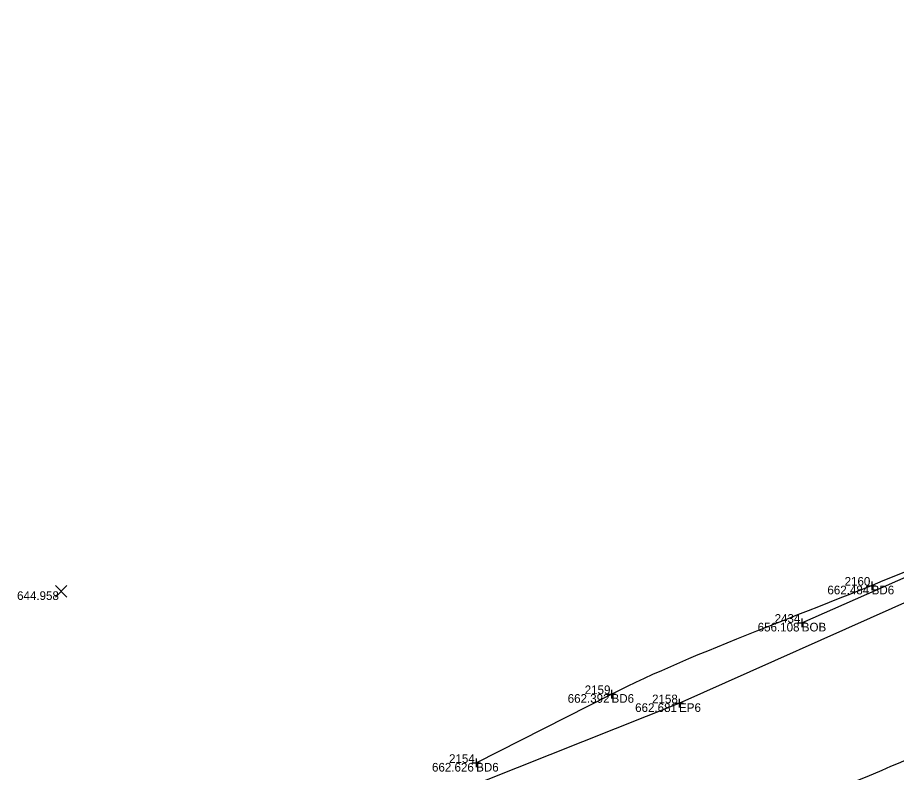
# Model space of a CAD drawing. Extents: x 2197382 to 2204062, y 634117 to 636522.
# Drawn here: x 2202361.4 to 2202463, y 635224.5 to 635311.8 of the extents above; entities that cross this region are included whole.
import ezdxf

# ---------------------------------------------------------------- set-up
doc = ezdxf.new("R2010")
doc.units = 0
for name, color, linetype in [('_CIVIL_CONSTRUCTION', 7, 'Continuous'), ('BR_X_SV_Bottom_of_Beam', 7, 'Continuous'), ('BR_X_SV_Bottom_of_Beam_Text', 7, 'Continuous'), ('BR_X_SV_Deck_Top', 7, 'Continuous'), ('BR_X_SV_Deck_Top_Text', 7, 'Continuous'), ('GE_P_Alignment_100_Distances', 7, 'Continuous'), ('GE_X_Alignment', 7, 'Continuous'), ('RW_X_CL_100_Curve_Data', 7, 'Continuous'), ('SH_Border', 7, 'Continuous'), ('SH_Cut_Line', 7, 'Continuous'), ('SH_Data', 7, 'Continuous')]:
    doc.layers.add(name, color=color, linetype=linetype)

msp = doc.modelspace()

# ---------------------------------------------------------------- linework, layer by layer
at = {"layer": '_CIVIL_CONSTRUCTION'}
for p, q in [((2202460.13, 635246.62), (2202460.13, 635245.62)), ((2202459.63, 635246.12), (2202460.63, 635246.12)), ((2202460.13, 635246.12), (2202460.13, 635246.12)), ((2202452.05, 635242.33), (2202452.05, 635241.33)), ((2202451.55, 635241.83), (2202452.55, 635241.83)), ((2202452.05, 635241.83), (2202452.05, 635241.83)), ((2202429.55, 635233.59), (2202430.55, 635233.59)), ((2202430.05, 635234.09), (2202430.05, 635233.09)), ((2202430.05, 635233.59), (2202430.05, 635233.59)), ((2202437.36, 635232.53), (2202438.36, 635232.53)), ((2202437.86, 635233.03), (2202437.86, 635232.03)), ((2202437.86, 635232.53), (2202437.86, 635232.53)), ((2202414.4, 635226.14), (2202414.4, 635225.14)), ((2202413.9, 635225.64), (2202414.9, 635225.64)), ((2202414.4, 635225.64), (2202414.4, 635225.64))]:
    msp.add_line(p, q, dxfattribs=at)
at = {"layer": 'BR_X_SV_Bottom_of_Beam'}
msp.add_lwpolyline([(2202452.05, 635241.83), (2202486.67, 635257.09), (2202513.32, 635270.74)], dxfattribs=at)
at = {"layer": 'BR_X_SV_Deck_Top'}
msp.add_line((2202414.4, 635225.64), (2202430.05, 635233.59), dxfattribs=at)
for points in [[(2202430.05, 635233.59), (2202439.74, 635238.51), (2202466.34, 635247.69), (2202507.17, 635268.03), (2202543.72, 635286.4), (2202574.88, 635303.71), (2202604.91, 635320.16), (2202634.13, 635339.4), (2202663.02, 635358.59), (2202692.44, 635376.51), (2202729.25, 635404.45), (2202755.81, 635426.42), (2202769.74, 635438.84)], [(2202458.05, 635216.68), (2202477.12, 635219.98), (2202511.72, 635243.78), (2202554.96, 635262.3), (2202588.01, 635280.67), (2202608.34, 635292.39), (2202640.83, 635312.14), (2202668.15, 635329.95), (2202698.57, 635351.31), (2202722.13, 635368.65), (2202754.6, 635393.43), (2202777.49, 635412.29), (2202789.61, 635422.64)]]:
    msp.add_open_spline(points, degree=3, dxfattribs=at)
at = {"layer": 'GE_P_Alignment_100_Distances'}
for p, q in [((2202437.86, 635232.53), (2202483.16, 635252.76)), ((2202405.09, 635219.54), (2202437.86, 635232.53))]:
    msp.add_line(p, q, dxfattribs=at)
for points in [[(2202457.67, 635223.28), (2202466.48, 635226.87), (2202500.46, 635242.35), (2202539.48, 635261.18), (2202573.06, 635279.52), (2202585.61, 635286.63), (2202599.84, 635294.84), (2202617.62, 635305.23), (2202642.29, 635320.4), (2202667.37, 635336.77), (2202691.72, 635353.63), (2202713.41, 635369.4), (2202739.64, 635388.97), (2202758.66, 635404.28), (2202770.06, 635413.81)], [(2202381.16, 635210.32), (2202366.1, 635204.72), (2202334.8, 635194.56), (2202286.96, 635182.66), (2202239.06, 635169.83), (2202190.57, 635161.31), (2202142.09, 635153.59), (2202092.91, 635148.21), (2202043.66, 635145.11), (2201994.31, 635143.9), (2201945.2, 635145.32), (2201896.27, 635148.27), (2201847.56, 635154.73), (2201798.82, 635161.43), (2201750.63, 635171.43), (2201702.91, 635182.55), (2201655.93, 635196.35), (2201609.49, 635212.58), (2201563.54, 635230.53), (2201517.8, 635250.11), (2201472.75, 635271.46), (2201426.49, 635290.37), (2201396.61, 635304.57), (2201381.57, 635311.27)], [(2202386.45, 635195.59), (2202370.91, 635189.75), (2202339.13, 635180.04), (2202291.09, 635166.72), (2202242.56, 635154.7), (2202193.6, 635144.9), (2202144.21, 635137.83), (2202094.71, 635131.91), (2202044.78, 635129.37), (2201994.9, 635127.35), (2201945.05, 635129.12), (2201895.29, 635131.98), (2201845.71, 635138.04), (2201796.31, 635145.15), (2201747.25, 635154.67), (2201698.84, 635166.79), (2201650.88, 635180.71), (2201603.87, 635197.49), (2201557.29, 635215.61), (2201511.45, 635235.48), (2201465.51, 635255.02), (2201420.2, 635275.98), (2201389.78, 635289.5), (2201374.58, 635296.3)]]:
    msp.add_open_spline(points, degree=3, dxfattribs=at)
at = {"layer": 'GE_X_Alignment'}
for points in [[(2202397.01, 635220.75), (2202390.94, 635219.55), (2202370.91, 635209.9), (2202333.66, 635198.74), (2202286.3, 635185.91), (2202238.23, 635173.94), (2202190.11, 635164.74), (2202141.77, 635157.37), (2202092.76, 635151.86), (2202043.46, 635148.8), (2201994.27, 635147.52), (2201945.31, 635148.99), (2201896.77, 635151.89), (2201848.09, 635157.45), (2201799.55, 635164.97), (2201751.45, 635174.5), (2201703.93, 635186.11), (2201657.05, 635199.39), (2201610.65, 635215.73), (2201564.74, 635233.57), (2201519.24, 635253.33), (2201473.99, 635273.72), (2201428.46, 635294.12), (2201398.16, 635307.71), (2201382.96, 635314.43)], [(2202389.25, 635188.21), (2202373.6, 635181.86), (2202342.05, 635172.03), (2202293.67, 635158.58), (2202244.91, 635146.21), (2202194.94, 635137.22), (2202145.31, 635129.1), (2202095.52, 635123.76), (2202045.13, 635120.93), (2201994.93, 635119.27), (2201944.5, 635120.71), (2201894.53, 635123.86), (2201844.41, 635129.5), (2201794.77, 635136.96), (2201745.53, 635147.41), (2201696.65, 635158.71), (2201648.35, 635173.37), (2201600.81, 635189.62), (2201553.51, 635207.06), (2201508.05, 635227.84), (2201462.09, 635247.86), (2201416.63, 635268.36), (2201386.21, 635281.9), (2201371.14, 635288.76)]]:
    msp.add_open_spline(points, degree=3, dxfattribs=at)
at = {"layer": 'RW_X_CL_100_Curve_Data'}
for p, q in [((2202365.75, 635244.81), (2202367.08, 635246.14)), ((2202365.75, 635246.14), (2202367.08, 635244.81))]:
    msp.add_line(p, q, dxfattribs=at)

# ---------------------------------------------------------------- texts
at = {"layer": 'BR_X_SV_Bottom_of_Beam_Text'}
for s, p in [('2434', (2202448.91, 635241.83)), ('656.108', (2202446.95, 635240.83)), ('BOB', (2202452.05, 635240.83))]:
    msp.add_text(s, height=1, dxfattribs=at).set_placement(p)
at = {"layer": 'BR_X_SV_Deck_Top_Text'}
for s, p in [('2160', (2202457, 635246.12)), ('662.484', (2202455.01, 635245.12)), ('BD6', (2202460.13, 635245.12)), ('2159', (2202426.95, 635233.59)), ('662.392', (2202424.98, 635232.59)), ('BD6', (2202430.05, 635232.59)), ('2154', (2202411.26, 635225.64)), ('662.626', (2202409.29, 635224.64)), ('BD6', (2202414.4, 635224.64))]:
    msp.add_text(s, height=1, dxfattribs=at).set_placement(p)
at = {"layer": 'SH_Border'}
msp.add_text('EP6', height=1, dxfattribs=at).set_placement((2202437.86, 635231.53))
at = {"layer": 'SH_Cut_Line'}
msp.add_text('2158', height=1, dxfattribs=at).set_placement((2202434.74, 635232.53))
at = {"layer": 'SH_Data'}
for s, p in [('644.958', (2202361.31, 635244.47)), ('662.681', (2202432.78, 635231.53))]:
    msp.add_text(s, height=1, dxfattribs=at).set_placement(p)

doc.saveas('drawing.dxf')
